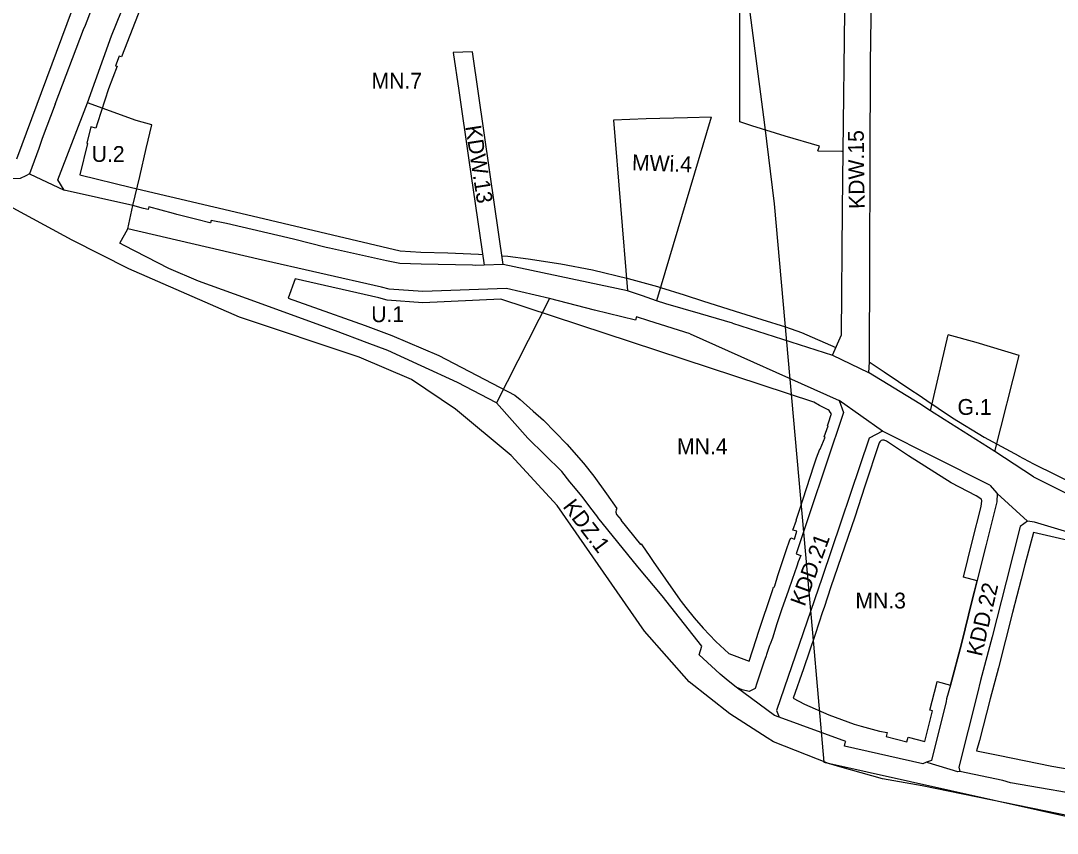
# Model space of a CAD drawing. Extents: x 7418991 to 7423142, y 5547704 to 5549547.
# Drawn here: x 7420359 to 7420686.6, y 5547752.5 to 5548009.3 of the extents above; entities that cross this region are included whole.
import ezdxf

# ---------------------------------------------------------------- set-up
doc = ezdxf.new("R2010")
doc.units = 0
for name, color, linetype in [('LIN_Linia Zabudowy Nieprzekraczalna', 7, 'Continuous'), ('LIN_linie_rozgraniczajace', 7, 'Continuous'), ('TRS_strefa ograniczen tunelu', 7, 'Continuous'), ('TXT_Oznaczenia_przeznaczen', 7, 'Continuous')]:
    doc.layers.add(name, color=color, linetype=linetype)

msp = doc.modelspace()

# ---------------------------------------------------------------- linework, layer by layer
at = {"layer": 'LIN_Linia Zabudowy Nieprzekraczalna'}
for p, q in [((7420357.76, 5547965.61), (7420407.03, 5548097.79)), ((7420377.64, 5547960.56), (7420393.99, 5547956.56)), ((7420445.75, 5547927.67), (7420443.58, 5547921.61)), ((7420609.64, 5547888.69), (7420510.77, 5547921.26)), ((7420491.18, 5547903.44), (7420515.17, 5547890.91)), ((7420604.06, 5547851.5), (7420605, 5547854.31)), ((7420589.21, 5547806.93), (7420590.28, 5547810.19)), ((7420582.8, 5547809.34), (7420589.21, 5547806.93))]:
    msp.add_line(p, q, dxfattribs=at)
for points in [[(7420397.43, 5548014.72), (7420396.85, 5548013.25), (7420391.77, 5548000.28), (7420390.82, 5547997.82)], [(7420390.82, 5547997.82), (7420390.11, 5547998.08), (7420388.98, 5547995), (7420389.46, 5547994.87), (7420386.72, 5547987.73)], [(7420386.72, 5547987.73), (7420383.22, 5547977.03), (7420382.77, 5547975.35)], [(7420382.77, 5547975.35), (7420381.17, 5547975.72), (7420379.9, 5547970.55), (7420380.12, 5547970.48), (7420377.64, 5547960.56)], [(7420393.99, 5547956.56), (7420432.19, 5547947.62), (7420478.89, 5547936.53)], [(7420478.89, 5547936.53), (7420485.45, 5547936.12), (7420493.99, 5547935.95), (7420503.68, 5547935.47), (7420504.95, 5547935.39)], [(7420511.11, 5547935), (7420513, 5547934.89), (7420519.38, 5547934.04), (7420529.66, 5547932.45), (7420539.7, 5547930.54), (7420550.95, 5547927.84), (7420560.3, 5547925.26), (7420561.22, 5547924.98), (7420568.73, 5547922.61), (7420574.84, 5547920.64), (7420586.44, 5547916.95), (7420593.22, 5547914.89), (7420600.71, 5547912.55), (7420605.73, 5547910.71), (7420616.63, 5547906.03)], [(7420510.77, 5547921.26), (7420486.05, 5547920.16), (7420474.84, 5547920.97), (7420472.23, 5547921.66), (7420445.75, 5547927.67)], [(7420443.58, 5547921.61), (7420450.08, 5547919.28), (7420467.91, 5547912.93), (7420476.33, 5547909.8), (7420491.18, 5547903.44)], [(7420627.21, 5547901.48), (7420631.88, 5547898.3), (7420640.93, 5547892.2), (7420642.33, 5547891.38), (7420647.12, 5547888.15), (7420648.28, 5547887.34), (7420649.01, 5547886.85), (7420653.47, 5547883.74), (7420663.54, 5547877.71), (7420674.41, 5547871.77)], [(7420515.17, 5547890.91), (7420516.82, 5547889.56), (7420521.01, 5547885.91)], [(7420521.01, 5547885.91), (7420524.25, 5547883.03), (7420531.58, 5547875.5), (7420536.91, 5547869.43), (7420540.1, 5547865.31), (7420544.11, 5547859.77), (7420547.38, 5547855.09)], [(7420614.03, 5547881.3), (7420614.31, 5547882.23), (7420615.17, 5547884.81), (7420615.24, 5547885.09), (7420614.88, 5547885.62), (7420614.49, 5547886.08), (7420614.17, 5547886.33), (7420611.51, 5547887.72), (7420609.64, 5547888.69)], [(7420610.54, 5547871.14), (7420611.54, 5547873.9), (7420611.71, 5547873.84), (7420613.23, 5547877.7), (7420612.95, 5547877.8), (7420614.19, 5547881.24), (7420614.03, 5547881.3)], [(7420662.49, 5547858.21), (7420661, 5547859.11), (7420653.1, 5547863.27), (7420639.64, 5547871.79), (7420632.67, 5547876.41), (7420631.88, 5547876.75), (7420631.33, 5547876.77), (7420630.96, 5547876.66), (7420630.54, 5547876.25), (7420630.28, 5547875.84), (7420625.77, 5547862.19), (7420625.78, 5547862.22), (7420622.58, 5547852.36), (7420615, 5547830.37), (7420612.98, 5547823.91), (7420612.37, 5547822.46), (7420610.07, 5547815.29), (7420606.37, 5547804.47), (7420603.11, 5547795.18), (7420606.69, 5547793.3), (7420614.42, 5547789.91), (7420622.41, 5547786.98), (7420624.67, 5547786.33), (7420630.45, 5547784.8), (7420632.84, 5547784.32), (7420632.54, 5547783.13), (7420639.06, 5547781.46), (7420639.44, 5547782.93), (7420644.7, 5547781.56), (7420647.21, 5547791.24), (7420646.33, 5547791.46), (7420648.54, 5547799.97), (7420648.67, 5547800.46), (7420652.9, 5547799.36), (7420656.32, 5547812.42), (7420659.73, 5547826.19), (7420661.26, 5547832.32), (7420657.02, 5547833.4), (7420659.71, 5547844.59), (7420662.51, 5547855.82), (7420662.75, 5547857.53), (7420662.63, 5547858.08), (7420662.49, 5547858.21)], [(7420605, 5547854.31), (7420609.82, 5547868.99), (7420610.54, 5547871.14)], [(7420674.38, 5547871.79), (7420679.11, 5547869.24), (7420686.18, 5547865.83), (7420698.03, 5547859.75)], [(7420547.38, 5547855.09), (7420547.17, 5547854.78), (7420547.05, 5547854.02), (7420547.26, 5547853.25), (7420548.73, 5547851.52), (7420548.63, 5547851.43), (7420554.88, 5547843.75), (7420555.12, 5547843.96)], [(7420596.94, 5547830.33), (7420597.16, 5547830.26), (7420597.32, 5547830.74), (7420598.34, 5547834.02), (7420600.97, 5547841.84), (7420601.08, 5547842.2), (7420602.03, 5547844.94), (7420602.38, 5547845.92), (7420603.55, 5547845.49), (7420604.28, 5547847.98), (7420603.08, 5547848.32), (7420604.2, 5547851.45), (7420604.06, 5547851.5)], [(7420695.53, 5547843.78), (7420679.06, 5547847.58), (7420676.36, 5547837.32), (7420675.16, 5547832.83), (7420672.41, 5547822.26), (7420668.04, 5547804.77), (7420665.4, 5547795.02), (7420662.03, 5547781.84), (7420661.13, 5547778.55), (7420667.97, 5547777.21), (7420684.85, 5547773.77), (7420690.32, 5547772.78)], [(7420555.12, 5547843.96), (7420555.53, 5547843.37), (7420557.63, 5547840.24), (7420558.93, 5547838.43), (7420562.81, 5547832.81), (7420567.42, 5547826.19)], [(7420590.28, 5547810.19), (7420591.52, 5547814.1), (7420592.14, 5547816.03), (7420596.58, 5547829.28), (7420596.94, 5547830.33)], [(7420567.42, 5547826.19), (7420567.76, 5547825.72), (7420569.17, 5547823.88), (7420571.84, 5547820.59), (7420574.68, 5547817.36), (7420578.72, 5547813.17), (7420582.8, 5547809.34)]]:
    msp.add_lwpolyline(points, dxfattribs=at)
at = {"layer": 'LIN_linie_rozgraniczajace'}
for p, q in [((7420361.82, 5547960.85), (7420372.77, 5547955.69)), ((7420526.12, 5547921.51), (7420509.41, 5547888.51)), ((7420583.97, 5547913.75), (7420615.54, 5547903.56)), ((7420570.62, 5547910.31), (7420617.67, 5547889.24)), ((7420646.55, 5547886.01), (7420652.14, 5547910.05)), ((7420615.54, 5547903.56), (7420626.96, 5547898.1)), ((7420643.13, 5547888.21), (7420626.96, 5547898.1)), ((7420617.67, 5547889.24), (7420619.04, 5547885.51)), ((7420679.05, 5547865.14), (7420708.53, 5547850.48)), ((7420667.61, 5547859.87), (7420677.19, 5547851.1)), ((7420597.84, 5547791.36), (7420598.68, 5547789.18))]:
    msp.add_line(p, q, dxfattribs=at)
for points in [[(7420369.89, 5547982.87), (7420378.84, 5548006.53), (7420379.5, 5548007.84), (7420387.56, 5548029.15), (7420392.91, 5548043.82), (7420394.63, 5548050.94), (7420402.34, 5548071.39), (7420403.27, 5548073.77), (7420404.07, 5548075.91), (7420405.93, 5548082.82), (7420408.96, 5548093.17), (7420410.08, 5548096.92), (7420414.66, 5548115.51), (7420420.33, 5548138.21), (7420423.83, 5548152.38)], [(7420691.26, 5547757.8), (7420643.94, 5547767.55), (7420631.35, 5547769.73), (7420617.94, 5547773.51), (7420614.35, 5547774.52), (7420596.92, 5547781.46), (7420594.97, 5547782.69), (7420583.1, 5547790.25), (7420570.22, 5547800.34), (7420556.17, 5547816.42), (7420528.6, 5547856.05), (7420513.96, 5547871.91), (7420496.43, 5547886.53), (7420482.51, 5547895.88), (7420465.97, 5547902.98), (7420428.16, 5547915.6), (7420393.16, 5547930.85), (7420375.21, 5547939.92), (7420335.32, 5547961.49), (7420325.12, 5547967), (7420017.42, 5548144.29)], [(7420610.97, 5547968.11), (7420611.41, 5547969.67), (7420600.58, 5547972.74), (7420590.12, 5547976.05), (7420586.3, 5547977.27), (7420586.32, 5548000.43), (7420586.33, 5548020.45), (7420586.34, 5548021.4), (7420586.47, 5548047.7), (7420586.49, 5548051.94), (7420586.49, 5548052.2), (7420586.66, 5548073.99), (7420607.92, 5548070.15), (7420619.96, 5548067.94)], [(7420372.77, 5547955.69), (7420370.76, 5547958.96), (7420380.13, 5547983.28), (7420387.72, 5548004.49), (7420393.75, 5548019.61), (7420397.8, 5548030.73), (7420400.96, 5548039.4), (7420410.18, 5548063.4), (7420412.12, 5548068.49)], [(7420615.54, 5547903.56), (7420618.4, 5547909.99), (7420618.78, 5547949.64), (7420618.96, 5547968.04), (7420619.44, 5548012.05), (7420619.46, 5548017.9), (7420619.32, 5548020.93), (7420619.68, 5548044.2), (7420619.81, 5548052.93), (7420619.96, 5548067.94), (7420628.5, 5548066.38), (7420627.45, 5547995.97), (7420627.21, 5547901.4), (7420626.96, 5547898.1)], [(7420511.52, 5547932.19), (7420507.27, 5547961.43), (7420501.76, 5547999.4), (7420495.71, 5547999.26), (7420497.47, 5547987.18), (7420500.67, 5547965.22), (7420505.43, 5547932.03)], [(7420369.89, 5547982.87), (7420365.77, 5547972.01), (7420364.73, 5547968.85), (7420361.82, 5547960.85), (7420360.58, 5547960.26)], [(7420394.44, 5547950.84), (7420396.61, 5547960.08), (7420398.68, 5547968.87), (7420400.47, 5547976.34), (7420395.48, 5547977.73), (7420380.13, 5547983.28)], [(7420577.25, 5547978.81), (7420569.72, 5547978.56), (7420556.67, 5547978.28), (7420546.32, 5547977.89), (7420550.75, 5547923.94)], [(7420577.25, 5547978.81), (7420559.97, 5547920.77)], [(7420610.97, 5547968.11), (7420618.52, 5547968.04), (7420618.96, 5547968.04)], [(7420360.58, 5547960.26), (7420358.8, 5547959.42), (7420354.1, 5547959.29), (7420340.9, 5547966.34)], [(7420399.47, 5547950.42), (7420399.27, 5547949.57), (7420397.83, 5547949.95), (7420394.44, 5547950.84), (7420372.77, 5547955.69)], [(7420390.37, 5547939.02), (7420392.83, 5547943.46), (7420394.44, 5547950.84)], [(7420478.86, 5547932.52), (7420474.58, 5547933.35), (7420456.64, 5547937.43), (7420455.54, 5547937.64), (7420445.19, 5547940.28), (7420424.06, 5547945.21), (7420419.23, 5547946.17), (7420419.03, 5547945.44), (7420418.81, 5547945.44), (7420414.69, 5547946.48), (7420408.39, 5547948.02), (7420407.24, 5547948.31), (7420399.47, 5547950.42)], [(7420553.28, 5547914.62), (7420540.38, 5547917.82), (7420526.12, 5547921.51), (7420512.57, 5547924.69), (7420486.11, 5547923.66), (7420475.42, 5547924.44), (7420473.06, 5547925.06), (7420434.05, 5547933.92), (7420392.83, 5547943.46)], [(7420497, 5547894.99), (7420485.6, 5547900.22), (7420475.06, 5547905.11), (7420468.5, 5547907.52), (7420458.54, 5547911.26), (7420430.34, 5547921.47), (7420415.24, 5547927.02), (7420405.76, 5547931.02), (7420391.7, 5547938.28), (7420390.37, 5547939.02)], [(7420511.52, 5547932.19), (7420505.43, 5547932.03), (7420502.77, 5547931.96), (7420501.77, 5547931.98), (7420485.6, 5547932.36), (7420478.86, 5547932.52)], [(7420583.97, 5547913.75), (7420573.84, 5547916.61), (7420562.9, 5547919.76), (7420559.97, 5547920.77), (7420555.51, 5547922.31), (7420550.75, 5547923.94), (7420511.52, 5547932.19)], [(7420570.62, 5547910.31), (7420557.5, 5547914.42), (7420553.57, 5547915.67), (7420553.28, 5547914.62)], [(7420666.89, 5547873.17), (7420674.59, 5547903.5), (7420661.01, 5547907.59), (7420652.14, 5547910.05)], [(7420554.07, 5547836.76), (7420541.36, 5547852.31), (7420541.37, 5547852.43), (7420538.92, 5547855.72), (7420537.98, 5547856.86), (7420536.31, 5547859), (7420534.33, 5547861.45), (7420532.58, 5547863.62), (7420530, 5547866.82), (7420519.23, 5547877.4), (7420509.41, 5547888.51), (7420497, 5547894.99)], [(7420665.29, 5547862.55), (7420647.67, 5547871.41), (7420631.32, 5547879.59), (7420617.67, 5547889.24)], [(7420619.04, 5547885.51), (7420608.32, 5547853.45), (7420604.13, 5547840.84)], [(7420679.05, 5547865.14), (7420666.89, 5547873.17), (7420650.83, 5547883.26), (7420646.55, 5547886.01), (7420643.13, 5547888.21)], [(7420631.32, 5547879.59), (7420627.13, 5547877.39), (7420612.26, 5547833.37), (7420597.84, 5547791.36)], [(7420665.29, 5547862.55), (7420667.61, 5547859.87), (7420667.5, 5547857.22), (7420664.03, 5547843.36), (7420659.73, 5547826.19), (7420656.32, 5547812.42), (7420652.9, 5547799.36), (7420651.56, 5547794.95), (7420651.53, 5547794.12), (7420646.86, 5547775.56), (7420645.3, 5547774.96)], [(7420679.43, 5547850.84), (7420677.19, 5547851.1), (7420674.86, 5547849.47), (7420670.49, 5547831.92), (7420666.03, 5547814.62), (7420662.31, 5547800.78), (7420661.42, 5547796.79), (7420655.46, 5547773.38), (7420655.8, 5547772.03)], [(7420802.95, 5547829.83), (7420778.55, 5547833.17), (7420754.72, 5547835.97), (7420745.87, 5547837.13), (7420728.04, 5547839.49), (7420724.08, 5547840.03), (7420709.97, 5547841.93), (7420701.54, 5547844.16), (7420679.43, 5547850.84)], [(7420604.13, 5547840.84), (7420605.58, 5547840.33), (7420604.72, 5547838.28), (7420604.26, 5547836.96), (7420602.79, 5547832.68), (7420601.63, 5547829.31), (7420599.5, 5547823.11), (7420597.94, 5547818.7), (7420596.56, 5547814.12), (7420595.84, 5547812.24), (7420595.7, 5547811.83), (7420594.74, 5547809.02), (7420594.61, 5547808.63), (7420593.9, 5547806.58), (7420593.16, 5547804.39), (7420591.68, 5547799.98), (7420591.11, 5547798.31), (7420589.19, 5547797.37), (7420587, 5547797.8), (7420585.11, 5547798.65)], [(7420597.27, 5547789.69), (7420585.11, 5547798.65), (7420582.6, 5547800.7), (7420580.06, 5547802.79), (7420578.55, 5547804.17), (7420573.39, 5547808.88), (7420574.22, 5547811.64), (7420561.69, 5547827.57), (7420554.07, 5547836.76)], [(7420619.39, 5547780.08), (7420619.61, 5547781.09), (7420619.82, 5547781.52), (7420598.68, 5547789.18), (7420597.27, 5547789.69)], [(7420645.84, 5547774.79), (7420645.3, 5547774.96), (7420644.09, 5547774.5), (7420619.39, 5547780.08)], [(7420711.87, 5547762.15), (7420709.6, 5547761.41), (7420705.44, 5547762.02), (7420699.52, 5547763.39), (7420698.32, 5547763.61), (7420693.9, 5547764.53), (7420687.7, 5547765.74), (7420684.1, 5547766.34), (7420671.79, 5547768.46), (7420669.45, 5547769.16), (7420655.8, 5547772.03), (7420655.15, 5547771.98), (7420645.84, 5547774.79)]]:
    msp.add_lwpolyline(points, dxfattribs=at)
at = {"layer": 'TRS_strefa ograniczen tunelu'}
msp.add_line((7420612.79, 5547774.96), (7420713.56, 5547752.53), dxfattribs=at)
msp.add_lwpolyline([(7420505.97, 5548397.28), (7420521.12, 5548341.79), (7420539.66, 5548271.1), (7420555.19, 5548204.71), (7420568.21, 5548140.79), (7420587.66, 5548025.67), (7420594.04, 5547976.4), (7420597.15, 5547951.42), (7420609.27, 5547815.84), (7420612.79, 5547774.96)], dxfattribs=at)

# ---------------------------------------------------------------- texts
at = {"layer": 'TXT_Oznaczenia_przeznaczen'}
for s, p in [('MN.7', (7420469.87, 5547987.81)), ('U.2', (7420381.43, 5547964.66)), ('U.1', (7420469.78, 5547914.03)), ('G.1', (7420655.08, 5547884.73)), ('MN.4', (7420566.43, 5547872.28)), ('MN.3', (7420622.8, 5547823.55))]:
    msp.add_text(s, height=5, dxfattribs=at).set_placement(p)
for s, rotation, p in [('KDW.13', 278.8195, (7420499.5, 5547975.85)), ('KDW.15', 90.7316, (7420625.75, 5547949.83)), ('MWi.4', 357.9964, (7420552.13, 5547962.03)), ('KDZ.1', 307.273, (7420530.13, 5547855.71)), ('KDD.21', 69.8174, (7420606.76, 5547823.96)), ('KDD.22', 77.0083, (7420662.75, 5547808.17))]:
    msp.add_text(s, height=5, rotation=rotation, dxfattribs=at).set_placement(p)

doc.saveas('drawing.dxf')
